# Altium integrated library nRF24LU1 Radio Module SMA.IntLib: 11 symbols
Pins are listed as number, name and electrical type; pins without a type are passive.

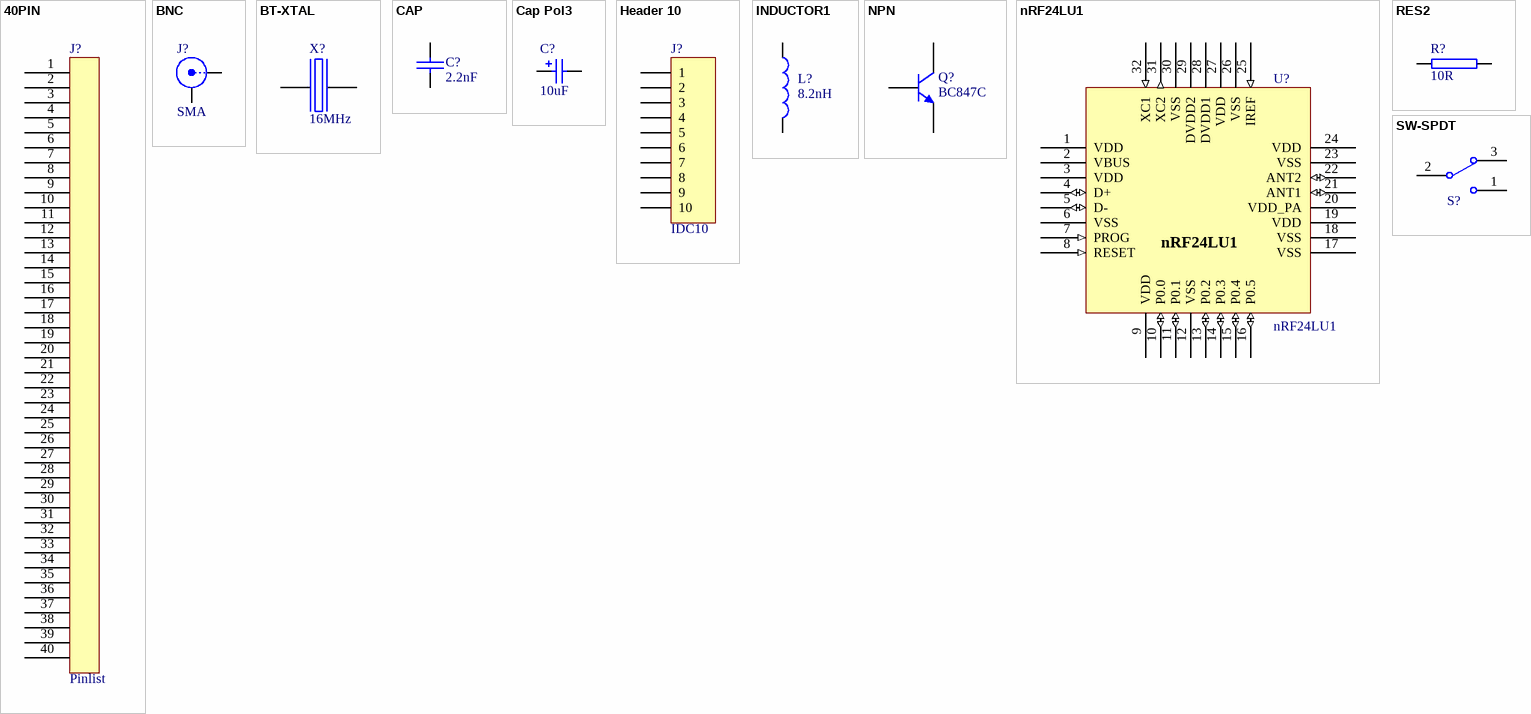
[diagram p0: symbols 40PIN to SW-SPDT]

## 40PIN
designator J?, comment value Pinlist  (hidden comment: Elfa 48-155-10)
footprint IDC40
footprint DIP40
pins: 1, 2, 3, 4, 5, 6, 7, 8, 9, 10, 11, 12, 13, 14, 15, 16, 17, 18, 19, 20, 21, 22, 23, 24, 25, 26, 27, 28, 29, 30, 31, 32, 33, 34, 35, 36, 37, 38, 39, 40

## BNC
designator J?, comment SMA
BNC Elbow Connector
footprint SMA connector horizontal
signal-integrity model Connector
pins: 1 X, 2 Y

## BT-XTAL
designator X?, comment value 16MHz  (hidden comment: TSX4025 16MHz, CL=9pF)
footprint BT-XTAL
pins: 1 inp, 2 GND hidden to GND, 3 out, 4 GND hidden to GND

## CAP
designator C?, comment value 2.2nF  (hidden comment: X7R, +/-10% 50V)
Part Field 1: 0402
footprint 0402s
pins: 1, 2

## Cap Pol3
designator C?, comment value 10uF  (hidden comment: Tantal  10V)
Polarized Capacitor (Surface Mount)
footprint C0805 (Chip Capacitor; Body 2.0 x 1.2 mm (LxW typ))
footprint C1206 (Chip Capacitor; Body 3.2 x 1.6 mm (LxW typ))
footprint 1825 (Chip Capacitor; Body 4.5 x 6.4 mm (LxW typ))
footprint C2225 (Chip Capacitor; Body 5.6 x 6.4 mm (LxW typ))
footprint 2220 (Chip Capacitor; Body 5.7 x 5.0 mm (LxW typ))
simulation model CAP (Capacitor)
signal-integrity model Cap Pol
pins: 1, 2
1 alternate drawing of the same symbol

## Header 10
designator J?, comment value IDC10  (hidden comment: Header 2x5 pin)
Header, 10-Pin
footprint IDC2x5
signal-integrity model Connector
pins: 1, 2, 3, 4, 5, 6, 7, 8, 9, 10

## INDUCTOR1
designator L?, comment value 8.2nH  (hidden comment: Chip inductor +/-5%)
Part Field 1: 0402
footprint 0402s
pins: 1, 2

## NPN
designator Q?, comment BC847C
NPN Bipolar Transistor
footprint SOT23 (SOT-23; 3 Leads; Body 3.1 x 2.5 mm, inc. leads (LxW max), Alternate Lead Configuration); pin to pad 2>3 3>2
simulation model NPN
signal-integrity model NPN
pins: 1 C, 2 B, 3 E

## nRF24LU1
designator U?
2.4GHz Transceiver with USB
footprint QFN32L/5x5
pins: 1 VDD (power) "Power supply (+3.3V DC) for de-coupling purposes", 2 VBUS (power) "USB power connection", 3 VDD (power) "Power supply (+3.3V DC) for de-coupling purposes", 4 D+ (io) "USB data +", 5 D- (io) "USB data -", 6 VSS (power) "Ground (0V)", 7 PROG (in) "Reserved for programming the flash", 8 RESET (in) "Reset for microcontroller, active low", 9 VDD (power) "Power supply (+3.3V DC) for de-coupling purposes", 10 P0.0 (io) "General purpose data Port 0, bit 0", 11 P0.1 (io) "General purpose data Port 0, bit 1", 12 VSS (power) "Ground (0V)", 13 P0.2 (io) "General purpose data Port 0, bit 2", 14 P0.3 (io) "General purpose data Port 0, bit 3", 15 P0.4 (io) "General purpose data Port 0, bit 4", 16 P0.5 (io) "General purpose data Port 0, bit 5", 17 VSS (power) "Ground (0V)", 18 VSS (power) "GND", 19 VDD (power) "Power supply (+3.3V DC) for de-coupling purposes", 20 VDD_PA (power) "Power Supply (+1.8V) to Power Amplifier", 21 ANT1 (io) "Antenna connection 1", 22 ANT2 (io) "Antenna connection 2", 23 VSS (power) "Ground (0V)", 24 VDD (power) "Power supply (+3.3V DC) for de-coupling purposes", 25 IREF (in) "Reference current", 26 VSS (power) "Ground (0V)", 27 VDD (power) "Power supply (+3.3V DC) for de-coupling purposes", 28 DVDD1 (power) "Positive Digital Supply output for de-coupling purposes", 29 DVDD2 (power) "Positive Digital Supply output for de-coupling purposes", 30 VSS (power) "Ground (0V)", 31 XC2 (out) "Crystal connection 2", 32 XC1 (in) "Crystal connection 1"

## RES2
designator R?, comment value 10R  (hidden comment: 5%)
Part Field 1: 0402
footprint 0402s
pins: 1, 2

## SW-SPDT
designator S?, comment ELFA 35-365-21  (value not drawn)
SPDT Subminiature Toggle Switch, Right Angle Mounting, Vertical Actuation; Revision 1: Jul-2002: Re-released for DXP Platform.; Revision 2: 17-Dec-2003: Schematic revised, PCB Footprint replaced.; Value: EAO type 1K2 straight pins
footprint TL36WW15050
footprint swmini2
footprint SW mini2
pins: 1, 2, 3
